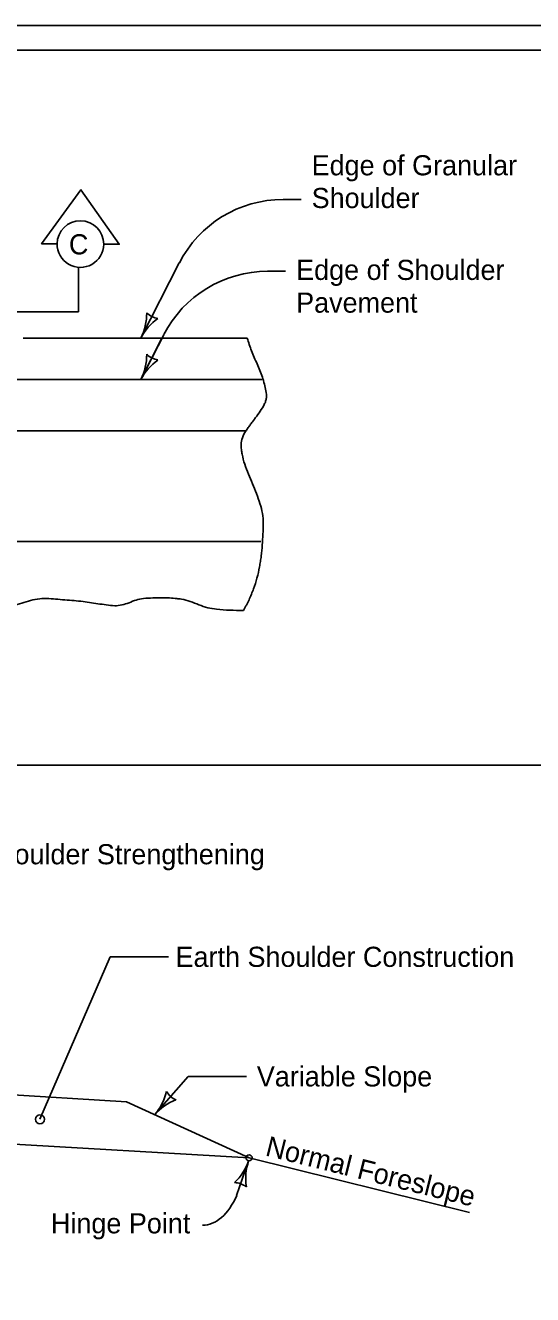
# Model space of a CAD drawing. Extents: x 10133 to 81668, y 5848 to 11018.
# Drawn here: x 11807 to 12210, y 8936 to 9944 of the extents above; entities that cross this region are included whole.
import ezdxf

# ---------------------------------------------------------------- set-up
doc = ezdxf.new("R2010")
doc.units = 0
for name, color, linetype in [('dsnStdLineWork', 7, 'Continuous'), ('dsnStdNote', 7, 'Continuous'), ('dsnStdPattern', 7, 'Continuous'), ('dsnStdSection', 7, 'Continuous'), ('dsnStdShading', 7, 'Continuous'), ('SheetBorder', 7, 'Continuous'), ('SheetText', 7, 'Continuous'), ('ShtPlotShapeBatchPrint', 7, 'Continuous')]:
    doc.layers.add(name, color=color, linetype=linetype)

msp = doc.modelspace()

# ---------------------------------------------------------------- linework, layer by layer
at = {"layer": 'dsnStdLineWork'}
for p, q in [((11805.5, 9695.6), (11983.4, 9695.6)), ((11915.2, 9694.5), (11898.9, 9662.7)), ((10347.6, 9662.7), (11995.1, 9662.7)), ((10368.9, 9622), (11982.7, 9622)), ((11753, 9097.2), (11887.7, 9088.8)), ((11887.7, 9088.8), (11984.8, 9044.4)), ((11984.8, 9044.4), (11408.7, 9077.6)), ((11984.8, 9044.4), (12159.8, 9001))]:
    msp.add_line(p, q, dxfattribs=at)
msp.add_ellipse((11984.8, 9044.4), major_axis=(2.58, 0), ratio=0.913811, dxfattribs=at)
for points in [[(11983.4, 9695.6), (11986.8, 9685.5), (11991.2, 9675.1), (11995.4, 9664.5), (11997, 9659.1), (11998.2, 9653.6), (11998.6, 9648.2), (11998.4, 9646.9), (11998, 9645.5), (11996.9, 9642.9), (11990, 9632.4), (11988.1, 9629.8), (11986.1, 9627.2), (11984.2, 9624.5), (11982.3, 9621.9), (11979.6, 9616.5), (11978.6, 9611), (11978.8, 9607.1), (11979.4, 9603.3), (11981.4, 9595.5), (11987.5, 9579.9), (11993.5, 9564.1), (11995.4, 9556.3), (11996.1, 9548.4), (11995.8, 9539.9), (11995.3, 9531.2), (11994.5, 9522.5), (11993.8, 9518.1), (11993.1, 9513.8), (11991.1, 9505), (11988.4, 9496.4), (11984.8, 9487.8), (11982.7, 9483.5), (11981.5, 9481.3), (11980.3, 9479.2)], [(11700.5, 9482.9), (11702.5, 9483), (11710.1, 9483.5), (11717.7, 9484.2), (11725.2, 9485), (11732.8, 9485.9), (11737.5, 9486.9), (11742.2, 9488.3), (11746.9, 9489.7), (11749.2, 9490.2), (11751.6, 9490.4), (11758.1, 9490.4), (11764.7, 9489.8), (11771.3, 9488.7), (11777.8, 9487.6), (11781.8, 9486.7), (11785.8, 9485.4), (11789.8, 9484.3), (11793.8, 9483.6), (11797.3, 9483.6), (11800.9, 9484.1), (11808, 9486), (11815.1, 9488), (11822.3, 9488.7), (11836.8, 9487.8), (11851.4, 9486.5), (11858.1, 9485.6), (11864.8, 9484.6), (11871.5, 9483.7), (11878.2, 9483), (11883.9, 9483.6), (11889.6, 9485.4), (11895.3, 9487.5), (11901, 9488.7), (11908.5, 9489.2), (11916.1, 9489.4), (11927.5, 9488.7), (11931.2, 9488.2), (11938.2, 9486.3), (11945.1, 9483.8), (11952, 9481.4), (11959.1, 9480.2), (11980.3, 9479.2)]]:
    msp.add_spline(points, degree=3, dxfattribs=at)
at = {"layer": 'dsnStdNote'}
msp.add_circle((11818.9, 9075), 3.54, dxfattribs=at)
msp.add_circle((11818.9, 9075), 3.54, dxfattribs=at)
at = {"layer": 'dsnStdPattern'}
for p, q in [((11849.5, 9716.5), (11849.5, 9751.9)), ((11849.5, 9716.5), (11849.5, 9751.9)), ((11761.4, 9716.5), (11849.5, 9716.5)), ((11761.4, 9716.5), (11849.5, 9716.5))]:
    msp.add_line(p, q, dxfattribs=at)
msp.add_lwpolyline([(11869.5, 9770.2), (11881.8, 9770.1), (11851.4, 9813.5), (11820.2, 9770.6), (11832.5, 9770.5)], dxfattribs=at)
for start, end in [(359.4792, 179.4775), (179.4775, 359.4792)]:
    msp.add_arc((11851, 9770.3), 18.5, start, end, dxfattribs=at)
at = {"layer": 'dsnStdSection'}
for p, q in [((12011.8, 9805.8), (12026.1, 9805.8)), ((12011.8, 9805.8), (12026.1, 9805.8)), ((11929.5, 9755.4), (11898.9, 9695.6)), ((11929.5, 9755.4), (11898.9, 9695.6)), ((11999.5, 9748.7), (12013.8, 9748.7)), ((11999.5, 9748.7), (12013.8, 9748.7)), ((11917.2, 9698.3), (11898.9, 9662.7)), ((11917.2, 9698.3), (11898.9, 9662.7))]:
    msp.add_line(p, q, dxfattribs=at)
for centre, radius, start, end in [((12011.8, 9713.3), 92.4, 90, 152.9341), ((12011.8, 9713.3), 92.4, 90, 152.9341), ((11999.5, 9656.3), 92.4, 90, 152.9341), ((11999.5, 9656.3), 92.4, 90, 152.9341), ((11861.1, 9715), 42.5, 332.9341, 1.0066), ((11861.1, 9715), 42.5, 332.9341, 1.0066), ((11936.8, 9676.3), 42.5, 124.8616, 152.9341), ((11936.8, 9676.3), 42.5, 124.8616, 152.9341), ((11915.2, 9727.4), 16.4, 225.2008, 260.6675), ((11915.2, 9727.4), 16.4, 225.2008, 260.6675), ((11861.1, 9682), 42.5, 332.9341, 1.0066), ((11861.1, 9682), 42.5, 332.9341, 1.0066), ((11915.2, 9694.4), 16.4, 225.2008, 260.6675), ((11915.2, 9694.4), 16.4, 225.2008, 260.6675), ((11936.8, 9643.3), 42.5, 124.8616, 152.9341), ((11936.8, 9643.3), 42.5, 124.8616, 152.9341)]:
    msp.add_arc(centre, radius, start, end, dxfattribs=at)
at = {"layer": 'dsnStdShading'}
for p, q in [((10352.3, 9534.1), (11994.3, 9534.1)), ((12307.8, 9356.4), (10152.2, 9356.4))]:
    msp.add_line(p, q, dxfattribs=at)
at = {"layer": 'SheetBorder'}
msp.add_lwpolyline([(10132.5, 9944), (13267.5, 9944), (13267.5, 7924), (10132.5, 7924)], close=True, dxfattribs=at)
at = {"layer": 'SheetText'}
for p, q in [((11818.9, 9075), (11874.6, 9204.1)), ((11874.6, 9204.1), (11921, 9204.1)), ((11909.9, 9078.7), (11936.5, 9109.1)), ((11936.5, 9109.1), (11982.9, 9109.1)), ((11975, 9014.4), (11984.5, 9042))]:
    msp.add_line(p, q, dxfattribs=at)
for centre, radius, start, end in [((11877.9, 9106.6), 42.5, 318.8454, 346.9178), ((11933.4, 9105.5), 16.4, 211.112, 246.5787), ((11941.9, 9050.7), 42.5, 110.7729, 138.8454), ((11944.3, 9055.8), 42.5, 312.9788, 341.0513), ((12024.7, 9028.2), 42.5, 161.0513, 189.1238), ((11972.9, 9008.3), 16.4, 53.3179, 88.7846)]:
    msp.add_arc(centre, radius, start, end, dxfattribs=at)
msp.add_ellipse((11947.9, 9052.3), major_axis=(0, 61.5), ratio=0.559383, start_param=3.141593, end_param=4.048985, dxfattribs=at)
at = {"layer": 'ShtPlotShapeBatchPrint'}
msp.add_line((10152.2, 9924.4), (13247.9, 9924.4), dxfattribs=at)

# ---------------------------------------------------------------- texts
at = {"layer": 'dsnStdPattern'}
msp.add_text('C', height=16, dxfattribs=at).set_placement((11841.9, 9762.1))
msp.add_text('C', height=16, dxfattribs=at).set_placement((11841.9, 9762.1))
at = {"layer": 'dsnStdSection'}
for s, p in [('Edge of Granular', (12034.5, 9824.9)), ('Edge of Granular', (12034.5, 9824.9)), ('Shoulder', (12034.5, 9798.9)), ('Shoulder', (12034.5, 9798.9)), ('Edge of Shoulder', (12022.2, 9741.8)), ('Edge of Shoulder', (12022.2, 9741.8)), ('Pavement', (12022.2, 9715.8)), ('Pavement', (12022.2, 9715.8))]:
    msp.add_text(s, height=16, dxfattribs=at).set_placement(p)
at = {"layer": 'SheetText'}
for s, p in [('Edge of Shoulder Strengthening', (11692.8, 9277.6)), ('Earth Shoulder Construction', (11926.5, 9196.1)), ('Variable Slope', (11991, 9101.1)), ('Hinge Point', (11827.6, 8984.4))]:
    msp.add_text(s, height=16, dxfattribs=at).set_placement(p)
msp.add_text('Normal Foreslope', height=16, rotation=346.0988, dxfattribs=at).set_placement((11997, 9046.4))

doc.saveas('drawing.dxf')
